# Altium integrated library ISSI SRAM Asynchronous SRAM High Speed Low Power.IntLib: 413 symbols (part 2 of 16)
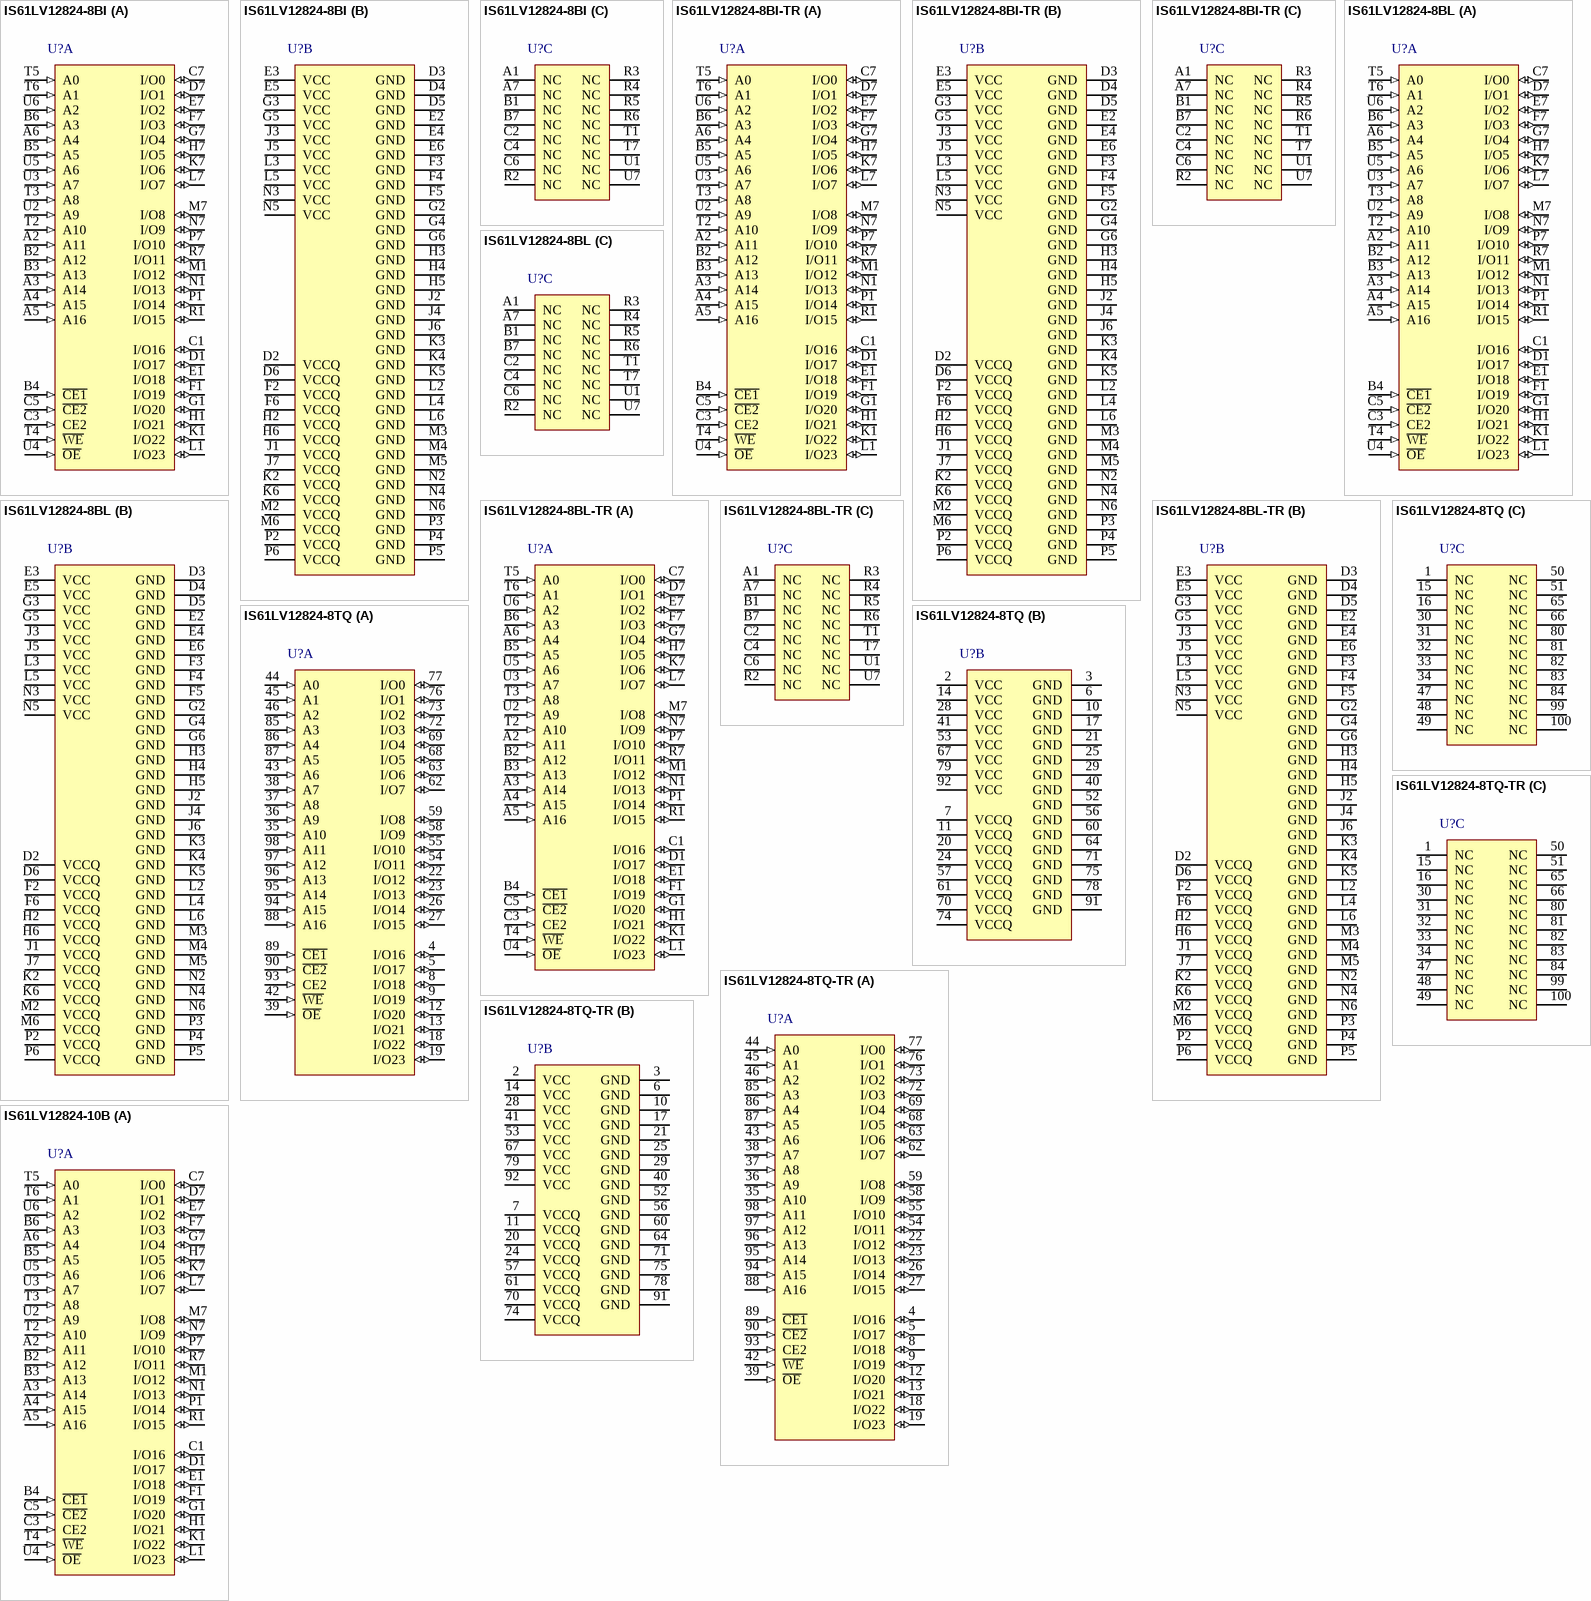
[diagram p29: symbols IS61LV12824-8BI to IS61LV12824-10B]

## IS61LV12824-8BI
designator U?
3 M High Speed CMOS SRAM with 3.3 V Supply, 128 K x 24, -40 to 85 degC, 119-Pin BGA (PBGA-119); Manufacturer: Integrated Silicon Solution Inc (ISSI); PartNumber: IS61LV12824-8BI; Density: 3M; Packing: Tray / Tube; Speed (ns): 8
footprint ISSI-PBGA-119-14000X22000DE_A (BGA, 119-Balls, Body 22x14mm, Pitch 1.27mm)
part A pins: A2 A11 (in) "Address Inputs", A3 A14 (in) "Address Inputs", A4 A15 (in) "Address Inputs", A5 A16 (in) "Address Inputs", A6 A4 (in) "Address Inputs", B2 A12 (in) "Address Inputs", B3 A13 (in) "Address Inputs", B4 ~{CE1} (in) "Chip Enable Input LOW", B5 A5 (in) "Address Input", B6 A3 (in) "Address Input", C1 I/O16 (io) "Data Inputs/Outputs", C3 CE2 (in) "Chip Enable Input HIGH", C5 ~{CE2} (in) "Chip Enable Input LOW", C7 I/O0 (io) "Data Inputs/Outputs", D1 I/O17 (io) "Data Inputs/Outputs", D7 I/O1 (io) "Data Inputs/Outputs", E1 I/O18 (io) "Data Inputs/Outputs", E7 I/O2 (io) "Data Inputs/Outputs", F1 I/O19 (io) "Data Inputs/Outputs", F7 I/O3 (io) "Data Inputs/Outputs", G1 I/O20 (io) "Data Inputs/Outputs", G7 I/O4 (io) "Data Inputs/Outputs", H1 I/O21 (io) "Data Inputs/Outputs", H7 I/O5 (io) "Data Inputs/Outputs", K1 I/O22 (io) "Data Inputs/Outputs", K7 I/O6 (io) "Data Inputs/Outputs", L1 I/O23 (io) "Data Inputs/Outputs", L7 I/O7 (io) "Data Inputs/Outputs", M1 I/O12 (io) "Data Inputs/Outputs", M7 I/O8 (io) "Data Inputs/Outputs", N1 I/O13 (io) "Data Inputs/Outputs", N7 I/O9 (io) "Data Inputs/Outputs", P1 I/O14 (io) "Data Inputs/Outputs", P7 I/O10 (io) "Data Inputs/Outputs", R1 I/O15 (io) "Data Inputs/Outputs", R7 I/O11 (io) "Data Inputs/Outputs", T2 A10 (in) "Address Inputs", T3 A8 (in) "Address Inputs", T4 ~{WE} (in) "Write Enable Input", T5 A0 (in) "Address Inputs", T6 A1 (in) "Address Inputs", U2 A9 (in) "Address Inputs", U3 A7 (in) "Address Inputs", U4 ~{OE} (in) "Output Enable Input", U5 A6 (in) "Address Inputs", U6 A2 (in) "Address Inputs"
part B pins: D2 VCCQ (power) "I/O Power", D3 GND (power) "Ground", D4 GND (power) "Ground", D5 GND (power) "Ground", D6 VCCQ (power) "I/O Power", E2 GND (power) "Ground", E3 VCC (power) "Power", E4 GND (power) "Ground", E5 VCC (power) "Power", E6 GND (power) "Ground", F2 VCCQ (power) "I/O Power", F3 GND (power) "Ground", F4 GND (power) "Ground", F5 GND (power) "Ground", F6 VCCQ (power) "I/O Power", G2 GND (power) "Ground", G3 VCC (power) "Power", G4 GND (power) "Ground", G5 VCC (power) "Power", G6 GND (power) "Ground", H2 VCCQ (power) "I/O Power", H3 GND (power) "Ground", H4 GND (power) "Ground", H5 GND (power) "Ground", H6 VCCQ (power) "I/O Power", J1 VCCQ (power) "I/O Power", J2 GND (power) "Ground", J3 VCC (power) "Power", J4 GND (power) "Ground", J5 VCC (power) "Power", J6 GND (power) "Ground", J7 VCCQ (power) "I/O Power", K2 VCCQ (power) "I/O Power", K3 GND (power) "Ground", K4 GND (power) "Ground", K5 GND (power) "Ground", K6 VCCQ (power) "I/O Power", L2 GND (power) "Ground", L3 VCC (power) "Power", L4 GND (power) "Ground", L5 VCC (power) "Power", L6 GND (power) "Ground", M2 VCCQ (power) "I/O Power", M3 GND (power) "Ground", M4 GND (power) "Ground", M5 GND (power) "Ground", M6 VCCQ (power) "I/O Power", N2 GND (power) "Ground", N3 VCC (power) "Power", N4 GND (power) "Ground", N5 VCC (power) "Power", N6 GND (power) "Ground", P2 VCCQ (power) "I/O Power", P3 GND (power) "Ground", P4 GND (power) "Ground", P5 GND (power) "Ground", P6 VCCQ (power) "I/O Power"
part C pins: A1 NC "No Connection", A7 NC "No Connection", B1 NC "No Connection", B7 NC "No Connection", C2 NC "No Connection", C4 NC "No Connection", C6 NC "No Connection", R2 NC "No Connection", R3 NC "No Connection", R4 NC "No Connection", R5 NC "No Connection", R6 NC "No Connection", T1 NC "No Connection", T7 NC "No Connection", U1 NC "No Connection", U7 NC "No Connection"

## IS61LV12824-8BI-TR
designator U?
3 M High Speed CMOS SRAM with 3.3 V Supply, 128 K x 24, -40 to 85 degC, 119-Pin BGA (PBGA-119); Manufacturer: Integrated Silicon Solution Inc (ISSI); PartNumber: IS61LV12824-8BI-TR; Density: 3M; Packing: Tape & Reel; Speed (ns): 8
footprint ISSI-PBGA-119-14000X22000DE_A (BGA, 119-Balls, Body 22x14mm, Pitch 1.27mm)
part A pins: A2 A11 (in) "Address Inputs", A3 A14 (in) "Address Inputs", A4 A15 (in) "Address Inputs", A5 A16 (in) "Address Inputs", A6 A4 (in) "Address Inputs", B2 A12 (in) "Address Inputs", B3 A13 (in) "Address Inputs", B4 ~{CE1} (in) "Chip Enable Input LOW", B5 A5 (in) "Address Input", B6 A3 (in) "Address Input", C1 I/O16 (io) "Data Inputs/Outputs", C3 CE2 (in) "Chip Enable Input HIGH", C5 ~{CE2} (in) "Chip Enable Input LOW", C7 I/O0 (io) "Data Inputs/Outputs", D1 I/O17 (io) "Data Inputs/Outputs", D7 I/O1 (io) "Data Inputs/Outputs", E1 I/O18 (io) "Data Inputs/Outputs", E7 I/O2 (io) "Data Inputs/Outputs", F1 I/O19 (io) "Data Inputs/Outputs", F7 I/O3 (io) "Data Inputs/Outputs", G1 I/O20 (io) "Data Inputs/Outputs", G7 I/O4 (io) "Data Inputs/Outputs", H1 I/O21 (io) "Data Inputs/Outputs", H7 I/O5 (io) "Data Inputs/Outputs", K1 I/O22 (io) "Data Inputs/Outputs", K7 I/O6 (io) "Data Inputs/Outputs", L1 I/O23 (io) "Data Inputs/Outputs", L7 I/O7 (io) "Data Inputs/Outputs", M1 I/O12 (io) "Data Inputs/Outputs", M7 I/O8 (io) "Data Inputs/Outputs", N1 I/O13 (io) "Data Inputs/Outputs", N7 I/O9 (io) "Data Inputs/Outputs", P1 I/O14 (io) "Data Inputs/Outputs", P7 I/O10 (io) "Data Inputs/Outputs", R1 I/O15 (io) "Data Inputs/Outputs", R7 I/O11 (io) "Data Inputs/Outputs", T2 A10 (in) "Address Inputs", T3 A8 (in) "Address Inputs", T4 ~{WE} (in) "Write Enable Input", T5 A0 (in) "Address Inputs", T6 A1 (in) "Address Inputs", U2 A9 (in) "Address Inputs", U3 A7 (in) "Address Inputs", U4 ~{OE} (in) "Output Enable Input", U5 A6 (in) "Address Inputs", U6 A2 (in) "Address Inputs"
part B pins: D2 VCCQ (power) "I/O Power", D3 GND (power) "Ground", D4 GND (power) "Ground", D5 GND (power) "Ground", D6 VCCQ (power) "I/O Power", E2 GND (power) "Ground", E3 VCC (power) "Power", E4 GND (power) "Ground", E5 VCC (power) "Power", E6 GND (power) "Ground", F2 VCCQ (power) "I/O Power", F3 GND (power) "Ground", F4 GND (power) "Ground", F5 GND (power) "Ground", F6 VCCQ (power) "I/O Power", G2 GND (power) "Ground", G3 VCC (power) "Power", G4 GND (power) "Ground", G5 VCC (power) "Power", G6 GND (power) "Ground", H2 VCCQ (power) "I/O Power", H3 GND (power) "Ground", H4 GND (power) "Ground", H5 GND (power) "Ground", H6 VCCQ (power) "I/O Power", J1 VCCQ (power) "I/O Power", J2 GND (power) "Ground", J3 VCC (power) "Power", J4 GND (power) "Ground", J5 VCC (power) "Power", J6 GND (power) "Ground", J7 VCCQ (power) "I/O Power", K2 VCCQ (power) "I/O Power", K3 GND (power) "Ground", K4 GND (power) "Ground", K5 GND (power) "Ground", K6 VCCQ (power) "I/O Power", L2 GND (power) "Ground", L3 VCC (power) "Power", L4 GND (power) "Ground", L5 VCC (power) "Power", L6 GND (power) "Ground", M2 VCCQ (power) "I/O Power", M3 GND (power) "Ground", M4 GND (power) "Ground", M5 GND (power) "Ground", M6 VCCQ (power) "I/O Power", N2 GND (power) "Ground", N3 VCC (power) "Power", N4 GND (power) "Ground", N5 VCC (power) "Power", N6 GND (power) "Ground", P2 VCCQ (power) "I/O Power", P3 GND (power) "Ground", P4 GND (power) "Ground", P5 GND (power) "Ground", P6 VCCQ (power) "I/O Power"
part C pins: A1 NC "No Connection", A7 NC "No Connection", B1 NC "No Connection", B7 NC "No Connection", C2 NC "No Connection", C4 NC "No Connection", C6 NC "No Connection", R2 NC "No Connection", R3 NC "No Connection", R4 NC "No Connection", R5 NC "No Connection", R6 NC "No Connection", T1 NC "No Connection", T7 NC "No Connection", U1 NC "No Connection", U7 NC "No Connection"

## IS61LV12824-8BL
designator U?
3 M High Speed CMOS SRAM with 3.3 V Supply, 128 K x 24, 0 to 70 degC, 119-Pin BGA (PBGA-119), Pb-Free; Manufacturer: Integrated Silicon Solution Inc (ISSI); PartNumber: IS61LV12824-8BL; Density: 3M; Packing: Tray / Tube; Speed (ns): 8
footprint ISSI-PBGA-119-14000X22000DE_A (BGA, 119-Balls, Body 22x14mm, Pitch 1.27mm)
part A pins: A2 A11 (in) "Address Inputs", A3 A14 (in) "Address Inputs", A4 A15 (in) "Address Inputs", A5 A16 (in) "Address Inputs", A6 A4 (in) "Address Inputs", B2 A12 (in) "Address Inputs", B3 A13 (in) "Address Inputs", B4 ~{CE1} (in) "Chip Enable Input LOW", B5 A5 (in) "Address Input", B6 A3 (in) "Address Input", C1 I/O16 (io) "Data Inputs/Outputs", C3 CE2 (in) "Chip Enable Input HIGH", C5 ~{CE2} (in) "Chip Enable Input LOW", C7 I/O0 (io) "Data Inputs/Outputs", D1 I/O17 (io) "Data Inputs/Outputs", D7 I/O1 (io) "Data Inputs/Outputs", E1 I/O18 (io) "Data Inputs/Outputs", E7 I/O2 (io) "Data Inputs/Outputs", F1 I/O19 (io) "Data Inputs/Outputs", F7 I/O3 (io) "Data Inputs/Outputs", G1 I/O20 (io) "Data Inputs/Outputs", G7 I/O4 (io) "Data Inputs/Outputs", H1 I/O21 (io) "Data Inputs/Outputs", H7 I/O5 (io) "Data Inputs/Outputs", K1 I/O22 (io) "Data Inputs/Outputs", K7 I/O6 (io) "Data Inputs/Outputs", L1 I/O23 (io) "Data Inputs/Outputs", L7 I/O7 (io) "Data Inputs/Outputs", M1 I/O12 (io) "Data Inputs/Outputs", M7 I/O8 (io) "Data Inputs/Outputs", N1 I/O13 (io) "Data Inputs/Outputs", N7 I/O9 (io) "Data Inputs/Outputs", P1 I/O14 (io) "Data Inputs/Outputs", P7 I/O10 (io) "Data Inputs/Outputs", R1 I/O15 (io) "Data Inputs/Outputs", R7 I/O11 (io) "Data Inputs/Outputs", T2 A10 (in) "Address Inputs", T3 A8 (in) "Address Inputs", T4 ~{WE} (in) "Write Enable Input", T5 A0 (in) "Address Inputs", T6 A1 (in) "Address Inputs", U2 A9 (in) "Address Inputs", U3 A7 (in) "Address Inputs", U4 ~{OE} (in) "Output Enable Input", U5 A6 (in) "Address Inputs", U6 A2 (in) "Address Inputs"
part B pins: D2 VCCQ (power) "I/O Power", D3 GND (power) "Ground", D4 GND (power) "Ground", D5 GND (power) "Ground", D6 VCCQ (power) "I/O Power", E2 GND (power) "Ground", E3 VCC (power) "Power", E4 GND (power) "Ground", E5 VCC (power) "Power", E6 GND (power) "Ground", F2 VCCQ (power) "I/O Power", F3 GND (power) "Ground", F4 GND (power) "Ground", F5 GND (power) "Ground", F6 VCCQ (power) "I/O Power", G2 GND (power) "Ground", G3 VCC (power) "Power", G4 GND (power) "Ground", G5 VCC (power) "Power", G6 GND (power) "Ground", H2 VCCQ (power) "I/O Power", H3 GND (power) "Ground", H4 GND (power) "Ground", H5 GND (power) "Ground", H6 VCCQ (power) "I/O Power", J1 VCCQ (power) "I/O Power", J2 GND (power) "Ground", J3 VCC (power) "Power", J4 GND (power) "Ground", J5 VCC (power) "Power", J6 GND (power) "Ground", J7 VCCQ (power) "I/O Power", K2 VCCQ (power) "I/O Power", K3 GND (power) "Ground", K4 GND (power) "Ground", K5 GND (power) "Ground", K6 VCCQ (power) "I/O Power", L2 GND (power) "Ground", L3 VCC (power) "Power", L4 GND (power) "Ground", L5 VCC (power) "Power", L6 GND (power) "Ground", M2 VCCQ (power) "I/O Power", M3 GND (power) "Ground", M4 GND (power) "Ground", M5 GND (power) "Ground", M6 VCCQ (power) "I/O Power", N2 GND (power) "Ground", N3 VCC (power) "Power", N4 GND (power) "Ground", N5 VCC (power) "Power", N6 GND (power) "Ground", P2 VCCQ (power) "I/O Power", P3 GND (power) "Ground", P4 GND (power) "Ground", P5 GND (power) "Ground", P6 VCCQ (power) "I/O Power"
part C pins: A1 NC "No Connection", A7 NC "No Connection", B1 NC "No Connection", B7 NC "No Connection", C2 NC "No Connection", C4 NC "No Connection", C6 NC "No Connection", R2 NC "No Connection", R3 NC "No Connection", R4 NC "No Connection", R5 NC "No Connection", R6 NC "No Connection", T1 NC "No Connection", T7 NC "No Connection", U1 NC "No Connection", U7 NC "No Connection"

## IS61LV12824-8BL-TR
designator U?
3 M High Speed CMOS SRAM with 3.3 V Supply, 128 K x 24, 0 to 70 degC, 119-Pin BGA (PBGA-119), Pb-Free; Manufacturer: Integrated Silicon Solution Inc (ISSI); PartNumber: IS61LV12824-8BL-TR; Density: 3M; Packing: Tape & Reel; Speed (ns): 8
footprint ISSI-PBGA-119-14000X22000DE_A (BGA, 119-Balls, Body 22x14mm, Pitch 1.27mm)
part A pins: A2 A11 (in) "Address Inputs", A3 A14 (in) "Address Inputs", A4 A15 (in) "Address Inputs", A5 A16 (in) "Address Inputs", A6 A4 (in) "Address Inputs", B2 A12 (in) "Address Inputs", B3 A13 (in) "Address Inputs", B4 ~{CE1} (in) "Chip Enable Input LOW", B5 A5 (in) "Address Input", B6 A3 (in) "Address Input", C1 I/O16 (io) "Data Inputs/Outputs", C3 CE2 (in) "Chip Enable Input HIGH", C5 ~{CE2} (in) "Chip Enable Input LOW", C7 I/O0 (io) "Data Inputs/Outputs", D1 I/O17 (io) "Data Inputs/Outputs", D7 I/O1 (io) "Data Inputs/Outputs", E1 I/O18 (io) "Data Inputs/Outputs", E7 I/O2 (io) "Data Inputs/Outputs", F1 I/O19 (io) "Data Inputs/Outputs", F7 I/O3 (io) "Data Inputs/Outputs", G1 I/O20 (io) "Data Inputs/Outputs", G7 I/O4 (io) "Data Inputs/Outputs", H1 I/O21 (io) "Data Inputs/Outputs", H7 I/O5 (io) "Data Inputs/Outputs", K1 I/O22 (io) "Data Inputs/Outputs", K7 I/O6 (io) "Data Inputs/Outputs", L1 I/O23 (io) "Data Inputs/Outputs", L7 I/O7 (io) "Data Inputs/Outputs", M1 I/O12 (io) "Data Inputs/Outputs", M7 I/O8 (io) "Data Inputs/Outputs", N1 I/O13 (io) "Data Inputs/Outputs", N7 I/O9 (io) "Data Inputs/Outputs", P1 I/O14 (io) "Data Inputs/Outputs", P7 I/O10 (io) "Data Inputs/Outputs", R1 I/O15 (io) "Data Inputs/Outputs", R7 I/O11 (io) "Data Inputs/Outputs", T2 A10 (in) "Address Inputs", T3 A8 (in) "Address Inputs", T4 ~{WE} (in) "Write Enable Input", T5 A0 (in) "Address Inputs", T6 A1 (in) "Address Inputs", U2 A9 (in) "Address Inputs", U3 A7 (in) "Address Inputs", U4 ~{OE} (in) "Output Enable Input", U5 A6 (in) "Address Inputs", U6 A2 (in) "Address Inputs"
part B pins: D2 VCCQ (power) "I/O Power", D3 GND (power) "Ground", D4 GND (power) "Ground", D5 GND (power) "Ground", D6 VCCQ (power) "I/O Power", E2 GND (power) "Ground", E3 VCC (power) "Power", E4 GND (power) "Ground", E5 VCC (power) "Power", E6 GND (power) "Ground", F2 VCCQ (power) "I/O Power", F3 GND (power) "Ground", F4 GND (power) "Ground", F5 GND (power) "Ground", F6 VCCQ (power) "I/O Power", G2 GND (power) "Ground", G3 VCC (power) "Power", G4 GND (power) "Ground", G5 VCC (power) "Power", G6 GND (power) "Ground", H2 VCCQ (power) "I/O Power", H3 GND (power) "Ground", H4 GND (power) "Ground", H5 GND (power) "Ground", H6 VCCQ (power) "I/O Power", J1 VCCQ (power) "I/O Power", J2 GND (power) "Ground", J3 VCC (power) "Power", J4 GND (power) "Ground", J5 VCC (power) "Power", J6 GND (power) "Ground", J7 VCCQ (power) "I/O Power", K2 VCCQ (power) "I/O Power", K3 GND (power) "Ground", K4 GND (power) "Ground", K5 GND (power) "Ground", K6 VCCQ (power) "I/O Power", L2 GND (power) "Ground", L3 VCC (power) "Power", L4 GND (power) "Ground", L5 VCC (power) "Power", L6 GND (power) "Ground", M2 VCCQ (power) "I/O Power", M3 GND (power) "Ground", M4 GND (power) "Ground", M5 GND (power) "Ground", M6 VCCQ (power) "I/O Power", N2 GND (power) "Ground", N3 VCC (power) "Power", N4 GND (power) "Ground", N5 VCC (power) "Power", N6 GND (power) "Ground", P2 VCCQ (power) "I/O Power", P3 GND (power) "Ground", P4 GND (power) "Ground", P5 GND (power) "Ground", P6 VCCQ (power) "I/O Power"
part C pins: A1 NC "No Connection", A7 NC "No Connection", B1 NC "No Connection", B7 NC "No Connection", C2 NC "No Connection", C4 NC "No Connection", C6 NC "No Connection", R2 NC "No Connection", R3 NC "No Connection", R4 NC "No Connection", R5 NC "No Connection", R6 NC "No Connection", T1 NC "No Connection", T7 NC "No Connection", U1 NC "No Connection", U7 NC "No Connection"

## IS61LV12824-8TQ
designator U?
3 M High Speed CMOS SRAM with 3.3 V Supply, 128 K x 24, 0 to 70 degC, 100-Pin QFP (TQFP-100); Manufacturer: Integrated Silicon Solution Inc (ISSI); PartNumber: IS61LV12824-8TQ; Density: 3M; Packing: Tray / Tube; Speed (ns): 8
footprint ISSI-TQFP-100-20000X14000DE_N (QFP, 100-Leads, Body 20x14mm, Pitch 0.65mm, IPC Medium Density)
part A pins: 4 I/O16 (io) "Data Input/Output", 5 I/O17 (io) "Data Input/Output", 8 I/O18 (io) "Data Input/Output", 9 I/O19 (io) "Data Input/Output", 12 I/O20 (io) "Data Input/Output", 13 I/O21 (io) "Data Input/Output", 18 I/O22 (io) "Data Input/Output", 19 I/O23 (io) "Data Input/Output", 22 I/O12 (io) "Data Input/Output", 23 I/O13 (io) "Data Input/Output", 26 I/O14 (io) "Data Input/Output", 27 I/O15 (io) "Data Input/Output", 35 A10 (in) "Address Input", 36 A9 (in) "Address Input", 37 A8 (in) "Address Input", 38 A7 (in) "Address Input", 39 ~{OE} (in) "Output Enable Input", 42 ~{WE} (in) "Write Enable Input", 43 A6 (in) "Address Input", 44 A0 (in) "Address Input", 45 A1 (in) "Address Input", 46 A2 (in) "Address Input", 54 I/O11 (io) "Data Input/Output", 55 I/O10 (io) "Data Input/Output", 58 I/O9 (io) "Data Input/Output", 59 I/O8 (io) "Data Input/Output", 62 I/O7 (io) "Data Input/Output", 63 I/O6 (io) "Data Input/Output", 68 I/O5 (io) "Data Input/Output", 69 I/O4 (io) "Data Input/Output", 72 I/O3 (io) "Data Input/Output", 73 I/O2 (io) "Data Input/Output", 76 I/O1 (io) "Data Input/Output", 77 I/O0 (io) "Data Input/Output", 85 A3 (in) "Address Input", 86 A4 (in) "Address Input", 87 A5 (in) "Address Input", 88 A16 (in) "Address Input", 89 ~{CE1} (in) "Chip Enable Input LOW", 90 ~{CE2} (in) "Chip Enable Input LOW", 93 CE2 (in) "Chip Enable Input HIGH", 94 A15 (in) "Address Input", 95 A14 (in) "Address Input", 96 A13 (in) "Address Input", 97 A12 (in) "Address Input", 98 A11 (in) "Address Input"
part B pins: 2 VCC (power) "Power", 3 GND (power) "Ground", 6 GND (power) "Ground", 7 VCCQ (power) "I/O Power", 10 GND (power) "Ground", 11 VCCQ (power) "I/O Power", 14 VCC (power) "Power", 17 GND (power) "Ground", 20 VCCQ (power) "I/O Power", 21 GND (power) "Ground", 24 VCCQ (power) "I/O Power", 25 GND (power) "Ground", 28 VCC (power) "Power", 29 GND (power) "Ground", 40 GND (power) "Ground", 41 VCC (power) "Power", 52 GND (power) "Ground", 53 VCC (power) "Power", 56 GND (power) "Ground", 57 VCCQ (power) "I/O Power", 60 GND (power) "Ground", 61 VCCQ (power) "I/O Power", 64 GND (power) "Ground", 67 VCC (power) "Power", 70 VCCQ (power) "I/O Power", 71 GND (power) "Ground", 74 VCCQ (power) "I/O Power", 75 GND (power) "Ground", 78 GND (power) "Ground", 79 VCC (power) "Power", 91 GND (power) "Ground", 92 VCC (power) "Power"
part C pins: 1 NC "No Connection", 15 NC "No Connection", 16 NC "No Connection", 30 NC "No Connection", 31 NC "No Connection", 32 NC "No Connection", 33 NC "No Connection", 34 NC "No Connection", 47 NC "No Connection", 48 NC "No Connection", 49 NC "No Connection", 50 NC "No Connection", 51 NC "No Connection", 65 NC "No Connection", 66 NC "No Connection", 80 NC "No Connection", 81 NC "No Connection", 82 NC "No Connection", 83 NC "No Connection", 84 NC "No Connection", 99 NC "No Connection", 100 NC "No Connection"

## IS61LV12824-8TQ-TR
designator U?
3 M High Speed CMOS SRAM with 3.3 V Supply, 128 K x 24, 0 to 70 degC, 100-Pin QFP (TQFP-100); Manufacturer: Integrated Silicon Solution Inc (ISSI); PartNumber: IS61LV12824-8TQ-TR; Density: 3M; Packing: Tape & Reel; Speed (ns): 8
footprint ISSI-TQFP-100-20000X14000DE_N (QFP, 100-Leads, Body 20x14mm, Pitch 0.65mm, IPC Medium Density)
part A pins: 4 I/O16 (io) "Data Input/Output", 5 I/O17 (io) "Data Input/Output", 8 I/O18 (io) "Data Input/Output", 9 I/O19 (io) "Data Input/Output", 12 I/O20 (io) "Data Input/Output", 13 I/O21 (io) "Data Input/Output", 18 I/O22 (io) "Data Input/Output", 19 I/O23 (io) "Data Input/Output", 22 I/O12 (io) "Data Input/Output", 23 I/O13 (io) "Data Input/Output", 26 I/O14 (io) "Data Input/Output", 27 I/O15 (io) "Data Input/Output", 35 A10 (in) "Address Input", 36 A9 (in) "Address Input", 37 A8 (in) "Address Input", 38 A7 (in) "Address Input", 39 ~{OE} (in) "Output Enable Input", 42 ~{WE} (in) "Write Enable Input", 43 A6 (in) "Address Input", 44 A0 (in) "Address Input", 45 A1 (in) "Address Input", 46 A2 (in) "Address Input", 54 I/O11 (io) "Data Input/Output", 55 I/O10 (io) "Data Input/Output", 58 I/O9 (io) "Data Input/Output", 59 I/O8 (io) "Data Input/Output", 62 I/O7 (io) "Data Input/Output", 63 I/O6 (io) "Data Input/Output", 68 I/O5 (io) "Data Input/Output", 69 I/O4 (io) "Data Input/Output", 72 I/O3 (io) "Data Input/Output", 73 I/O2 (io) "Data Input/Output", 76 I/O1 (io) "Data Input/Output", 77 I/O0 (io) "Data Input/Output", 85 A3 (in) "Address Input", 86 A4 (in) "Address Input", 87 A5 (in) "Address Input", 88 A16 (in) "Address Input", 89 ~{CE1} (in) "Chip Enable Input LOW", 90 ~{CE2} (in) "Chip Enable Input LOW", 93 CE2 (in) "Chip Enable Input HIGH", 94 A15 (in) "Address Input", 95 A14 (in) "Address Input", 96 A13 (in) "Address Input", 97 A12 (in) "Address Input", 98 A11 (in) "Address Input"
part B pins: 2 VCC (power) "Power", 3 GND (power) "Ground", 6 GND (power) "Ground", 7 VCCQ (power) "I/O Power", 10 GND (power) "Ground", 11 VCCQ (power) "I/O Power", 14 VCC (power) "Power", 17 GND (power) "Ground", 20 VCCQ (power) "I/O Power", 21 GND (power) "Ground", 24 VCCQ (power) "I/O Power", 25 GND (power) "Ground", 28 VCC (power) "Power", 29 GND (power) "Ground", 40 GND (power) "Ground", 41 VCC (power) "Power", 52 GND (power) "Ground", 53 VCC (power) "Power", 56 GND (power) "Ground", 57 VCCQ (power) "I/O Power", 60 GND (power) "Ground", 61 VCCQ (power) "I/O Power", 64 GND (power) "Ground", 67 VCC (power) "Power", 70 VCCQ (power) "I/O Power", 71 GND (power) "Ground", 74 VCCQ (power) "I/O Power", 75 GND (power) "Ground", 78 GND (power) "Ground", 79 VCC (power) "Power", 91 GND (power) "Ground", 92 VCC (power) "Power"
part C pins: 1 NC "No Connection", 15 NC "No Connection", 16 NC "No Connection", 30 NC "No Connection", 31 NC "No Connection", 32 NC "No Connection", 33 NC "No Connection", 34 NC "No Connection", 47 NC "No Connection", 48 NC "No Connection", 49 NC "No Connection", 50 NC "No Connection", 51 NC "No Connection", 65 NC "No Connection", 66 NC "No Connection", 80 NC "No Connection", 81 NC "No Connection", 82 NC "No Connection", 83 NC "No Connection", 84 NC "No Connection", 99 NC "No Connection", 100 NC "No Connection"

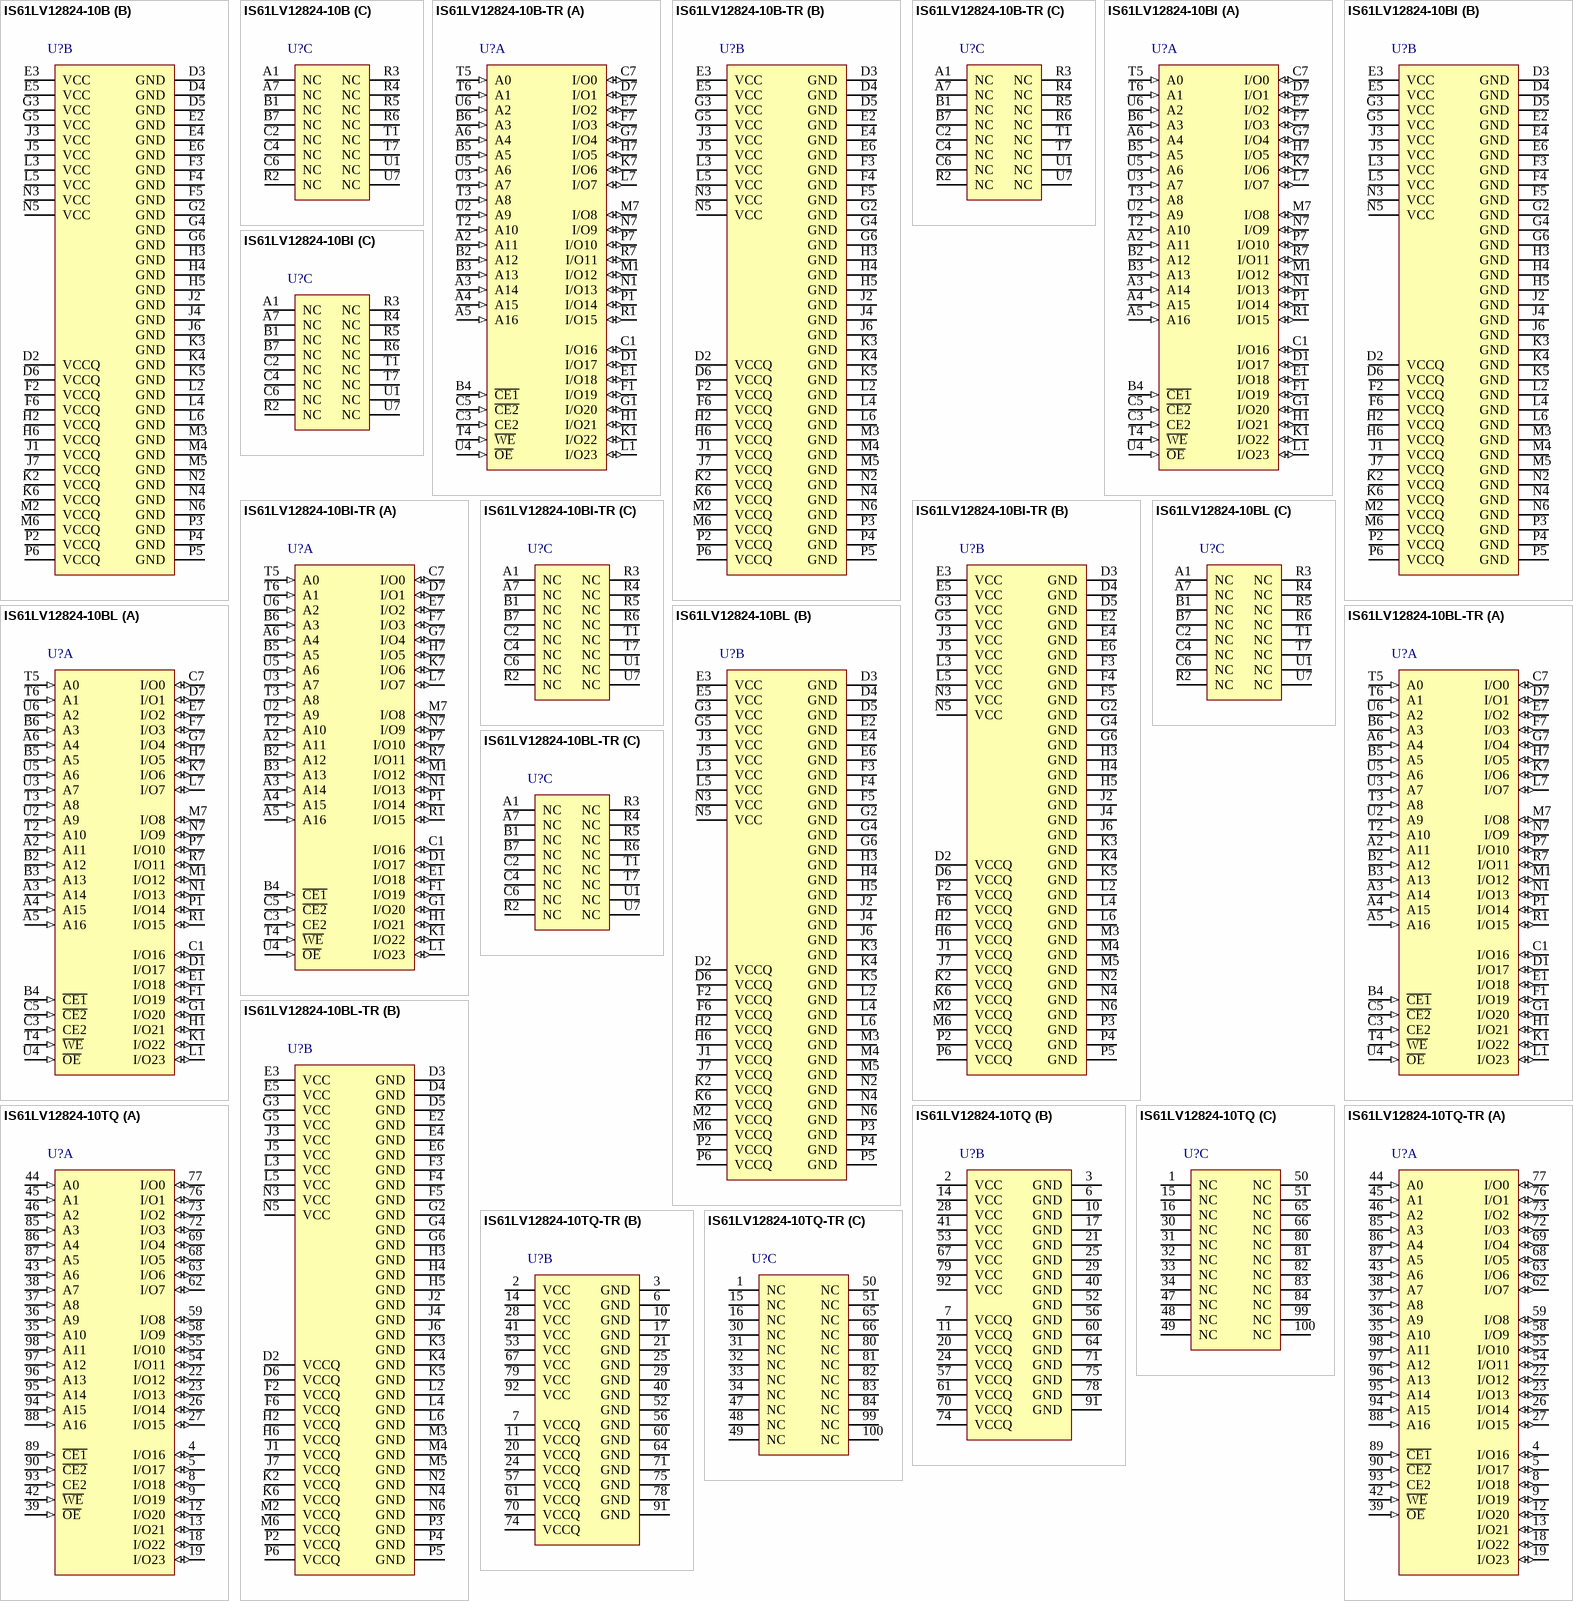
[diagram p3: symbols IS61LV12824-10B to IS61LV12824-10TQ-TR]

## IS61LV12824-10B
designator U?
3 M High Speed CMOS SRAM with 3.3 V Supply, 128 K x 24, 0 to 70 degC, 119-Pin BGA (PBGA-119); Manufacturer: Integrated Silicon Solution Inc (ISSI); PartNumber: IS61LV12824-10B; Density: 3M; Packing: Tray / Tube; Speed (ns): 10
footprint ISSI-PBGA-119-14000X22000DE_A (BGA, 119-Balls, Body 22x14mm, Pitch 1.27mm)
part A pins: A2 A11 (in) "Address Inputs", A3 A14 (in) "Address Inputs", A4 A15 (in) "Address Inputs", A5 A16 (in) "Address Inputs", A6 A4 (in) "Address Inputs", B2 A12 (in) "Address Inputs", B3 A13 (in) "Address Inputs", B4 ~{CE1} (in) "Chip Enable Input LOW", B5 A5 (in) "Address Input", B6 A3 (in) "Address Input", C1 I/O16 (io) "Data Inputs/Outputs", C3 CE2 (in) "Chip Enable Input HIGH", C5 ~{CE2} (in) "Chip Enable Input LOW", C7 I/O0 (io) "Data Inputs/Outputs", D1 I/O17 (io) "Data Inputs/Outputs", D7 I/O1 (io) "Data Inputs/Outputs", E1 I/O18 (io) "Data Inputs/Outputs", E7 I/O2 (io) "Data Inputs/Outputs", F1 I/O19 (io) "Data Inputs/Outputs", F7 I/O3 (io) "Data Inputs/Outputs", G1 I/O20 (io) "Data Inputs/Outputs", G7 I/O4 (io) "Data Inputs/Outputs", H1 I/O21 (io) "Data Inputs/Outputs", H7 I/O5 (io) "Data Inputs/Outputs", K1 I/O22 (io) "Data Inputs/Outputs", K7 I/O6 (io) "Data Inputs/Outputs", L1 I/O23 (io) "Data Inputs/Outputs", L7 I/O7 (io) "Data Inputs/Outputs", M1 I/O12 (io) "Data Inputs/Outputs", M7 I/O8 (io) "Data Inputs/Outputs", N1 I/O13 (io) "Data Inputs/Outputs", N7 I/O9 (io) "Data Inputs/Outputs", P1 I/O14 (io) "Data Inputs/Outputs", P7 I/O10 (io) "Data Inputs/Outputs", R1 I/O15 (io) "Data Inputs/Outputs", R7 I/O11 (io) "Data Inputs/Outputs", T2 A10 (in) "Address Inputs", T3 A8 (in) "Address Inputs", T4 ~{WE} (in) "Write Enable Input", T5 A0 (in) "Address Inputs", T6 A1 (in) "Address Inputs", U2 A9 (in) "Address Inputs", U3 A7 (in) "Address Inputs", U4 ~{OE} (in) "Output Enable Input", U5 A6 (in) "Address Inputs", U6 A2 (in) "Address Inputs"
part B pins: D2 VCCQ (power) "I/O Power", D3 GND (power) "Ground", D4 GND (power) "Ground", D5 GND (power) "Ground", D6 VCCQ (power) "I/O Power", E2 GND (power) "Ground", E3 VCC (power) "Power", E4 GND (power) "Ground", E5 VCC (power) "Power", E6 GND (power) "Ground", F2 VCCQ (power) "I/O Power", F3 GND (power) "Ground", F4 GND (power) "Ground", F5 GND (power) "Ground", F6 VCCQ (power) "I/O Power", G2 GND (power) "Ground", G3 VCC (power) "Power", G4 GND (power) "Ground", G5 VCC (power) "Power", G6 GND (power) "Ground", H2 VCCQ (power) "I/O Power", H3 GND (power) "Ground", H4 GND (power) "Ground", H5 GND (power) "Ground", H6 VCCQ (power) "I/O Power", J1 VCCQ (power) "I/O Power", J2 GND (power) "Ground", J3 VCC (power) "Power", J4 GND (power) "Ground", J5 VCC (power) "Power", J6 GND (power) "Ground", J7 VCCQ (power) "I/O Power", K2 VCCQ (power) "I/O Power", K3 GND (power) "Ground", K4 GND (power) "Ground", K5 GND (power) "Ground", K6 VCCQ (power) "I/O Power", L2 GND (power) "Ground", L3 VCC (power) "Power", L4 GND (power) "Ground", L5 VCC (power) "Power", L6 GND (power) "Ground", M2 VCCQ (power) "I/O Power", M3 GND (power) "Ground", M4 GND (power) "Ground", M5 GND (power) "Ground", M6 VCCQ (power) "I/O Power", N2 GND (power) "Ground", N3 VCC (power) "Power", N4 GND (power) "Ground", N5 VCC (power) "Power", N6 GND (power) "Ground", P2 VCCQ (power) "I/O Power", P3 GND (power) "Ground", P4 GND (power) "Ground", P5 GND (power) "Ground", P6 VCCQ (power) "I/O Power"
part C pins: A1 NC "No Connection", A7 NC "No Connection", B1 NC "No Connection", B7 NC "No Connection", C2 NC "No Connection", C4 NC "No Connection", C6 NC "No Connection", R2 NC "No Connection", R3 NC "No Connection", R4 NC "No Connection", R5 NC "No Connection", R6 NC "No Connection", T1 NC "No Connection", T7 NC "No Connection", U1 NC "No Connection", U7 NC "No Connection"

## IS61LV12824-10B-TR
designator U?
3 M High Speed CMOS SRAM with 3.3 V Supply, 128 K x 24, 0 to 70 degC, 119-Pin BGA (PBGA-119); Manufacturer: Integrated Silicon Solution Inc (ISSI); PartNumber: IS61LV12824-10B-TR; Density: 3M; Packing: Tape & Reel; Speed (ns): 10
footprint ISSI-PBGA-119-14000X22000DE_A (BGA, 119-Balls, Body 22x14mm, Pitch 1.27mm)
part A pins: A2 A11 (in) "Address Inputs", A3 A14 (in) "Address Inputs", A4 A15 (in) "Address Inputs", A5 A16 (in) "Address Inputs", A6 A4 (in) "Address Inputs", B2 A12 (in) "Address Inputs", B3 A13 (in) "Address Inputs", B4 ~{CE1} (in) "Chip Enable Input LOW", B5 A5 (in) "Address Input", B6 A3 (in) "Address Input", C1 I/O16 (io) "Data Inputs/Outputs", C3 CE2 (in) "Chip Enable Input HIGH", C5 ~{CE2} (in) "Chip Enable Input LOW", C7 I/O0 (io) "Data Inputs/Outputs", D1 I/O17 (io) "Data Inputs/Outputs", D7 I/O1 (io) "Data Inputs/Outputs", E1 I/O18 (io) "Data Inputs/Outputs", E7 I/O2 (io) "Data Inputs/Outputs", F1 I/O19 (io) "Data Inputs/Outputs", F7 I/O3 (io) "Data Inputs/Outputs", G1 I/O20 (io) "Data Inputs/Outputs", G7 I/O4 (io) "Data Inputs/Outputs", H1 I/O21 (io) "Data Inputs/Outputs", H7 I/O5 (io) "Data Inputs/Outputs", K1 I/O22 (io) "Data Inputs/Outputs", K7 I/O6 (io) "Data Inputs/Outputs", L1 I/O23 (io) "Data Inputs/Outputs", L7 I/O7 (io) "Data Inputs/Outputs", M1 I/O12 (io) "Data Inputs/Outputs", M7 I/O8 (io) "Data Inputs/Outputs", N1 I/O13 (io) "Data Inputs/Outputs", N7 I/O9 (io) "Data Inputs/Outputs", P1 I/O14 (io) "Data Inputs/Outputs", P7 I/O10 (io) "Data Inputs/Outputs", R1 I/O15 (io) "Data Inputs/Outputs", R7 I/O11 (io) "Data Inputs/Outputs", T2 A10 (in) "Address Inputs", T3 A8 (in) "Address Inputs", T4 ~{WE} (in) "Write Enable Input", T5 A0 (in) "Address Inputs", T6 A1 (in) "Address Inputs", U2 A9 (in) "Address Inputs", U3 A7 (in) "Address Inputs", U4 ~{OE} (in) "Output Enable Input", U5 A6 (in) "Address Inputs", U6 A2 (in) "Address Inputs"
part B pins: D2 VCCQ (power) "I/O Power", D3 GND (power) "Ground", D4 GND (power) "Ground", D5 GND (power) "Ground", D6 VCCQ (power) "I/O Power", E2 GND (power) "Ground", E3 VCC (power) "Power", E4 GND (power) "Ground", E5 VCC (power) "Power", E6 GND (power) "Ground", F2 VCCQ (power) "I/O Power", F3 GND (power) "Ground", F4 GND (power) "Ground", F5 GND (power) "Ground", F6 VCCQ (power) "I/O Power", G2 GND (power) "Ground", G3 VCC (power) "Power", G4 GND (power) "Ground", G5 VCC (power) "Power", G6 GND (power) "Ground", H2 VCCQ (power) "I/O Power", H3 GND (power) "Ground", H4 GND (power) "Ground", H5 GND (power) "Ground", H6 VCCQ (power) "I/O Power", J1 VCCQ (power) "I/O Power", J2 GND (power) "Ground", J3 VCC (power) "Power", J4 GND (power) "Ground", J5 VCC (power) "Power", J6 GND (power) "Ground", J7 VCCQ (power) "I/O Power", K2 VCCQ (power) "I/O Power", K3 GND (power) "Ground", K4 GND (power) "Ground", K5 GND (power) "Ground", K6 VCCQ (power) "I/O Power", L2 GND (power) "Ground", L3 VCC (power) "Power", L4 GND (power) "Ground", L5 VCC (power) "Power", L6 GND (power) "Ground", M2 VCCQ (power) "I/O Power", M3 GND (power) "Ground", M4 GND (power) "Ground", M5 GND (power) "Ground", M6 VCCQ (power) "I/O Power", N2 GND (power) "Ground", N3 VCC (power) "Power", N4 GND (power) "Ground", N5 VCC (power) "Power", N6 GND (power) "Ground", P2 VCCQ (power) "I/O Power", P3 GND (power) "Ground", P4 GND (power) "Ground", P5 GND (power) "Ground", P6 VCCQ (power) "I/O Power"
part C pins: A1 NC "No Connection", A7 NC "No Connection", B1 NC "No Connection", B7 NC "No Connection", C2 NC "No Connection", C4 NC "No Connection", C6 NC "No Connection", R2 NC "No Connection", R3 NC "No Connection", R4 NC "No Connection", R5 NC "No Connection", R6 NC "No Connection", T1 NC "No Connection", T7 NC "No Connection", U1 NC "No Connection", U7 NC "No Connection"

## IS61LV12824-10BI
designator U?
3 M High Speed CMOS SRAM with 3.3 V Supply, 128 K x 24, -40 to 85 degC, 119-Pin BGA (PBGA-119); Manufacturer: Integrated Silicon Solution Inc (ISSI); PartNumber: IS61LV12824-10BI; Density: 3M; Packing: Tray / Tube; Speed (ns): 10
footprint ISSI-PBGA-119-14000X22000DE_A (BGA, 119-Balls, Body 22x14mm, Pitch 1.27mm)
part A pins: A2 A11 (in) "Address Inputs", A3 A14 (in) "Address Inputs", A4 A15 (in) "Address Inputs", A5 A16 (in) "Address Inputs", A6 A4 (in) "Address Inputs", B2 A12 (in) "Address Inputs", B3 A13 (in) "Address Inputs", B4 ~{CE1} (in) "Chip Enable Input LOW", B5 A5 (in) "Address Input", B6 A3 (in) "Address Input", C1 I/O16 (io) "Data Inputs/Outputs", C3 CE2 (in) "Chip Enable Input HIGH", C5 ~{CE2} (in) "Chip Enable Input LOW", C7 I/O0 (io) "Data Inputs/Outputs", D1 I/O17 (io) "Data Inputs/Outputs", D7 I/O1 (io) "Data Inputs/Outputs", E1 I/O18 (io) "Data Inputs/Outputs", E7 I/O2 (io) "Data Inputs/Outputs", F1 I/O19 (io) "Data Inputs/Outputs", F7 I/O3 (io) "Data Inputs/Outputs", G1 I/O20 (io) "Data Inputs/Outputs", G7 I/O4 (io) "Data Inputs/Outputs", H1 I/O21 (io) "Data Inputs/Outputs", H7 I/O5 (io) "Data Inputs/Outputs", K1 I/O22 (io) "Data Inputs/Outputs", K7 I/O6 (io) "Data Inputs/Outputs", L1 I/O23 (io) "Data Inputs/Outputs", L7 I/O7 (io) "Data Inputs/Outputs", M1 I/O12 (io) "Data Inputs/Outputs", M7 I/O8 (io) "Data Inputs/Outputs", N1 I/O13 (io) "Data Inputs/Outputs", N7 I/O9 (io) "Data Inputs/Outputs", P1 I/O14 (io) "Data Inputs/Outputs", P7 I/O10 (io) "Data Inputs/Outputs", R1 I/O15 (io) "Data Inputs/Outputs", R7 I/O11 (io) "Data Inputs/Outputs", T2 A10 (in) "Address Inputs", T3 A8 (in) "Address Inputs", T4 ~{WE} (in) "Write Enable Input", T5 A0 (in) "Address Inputs", T6 A1 (in) "Address Inputs", U2 A9 (in) "Address Inputs", U3 A7 (in) "Address Inputs", U4 ~{OE} (in) "Output Enable Input", U5 A6 (in) "Address Inputs", U6 A2 (in) "Address Inputs"
part B pins: D2 VCCQ (power) "I/O Power", D3 GND (power) "Ground", D4 GND (power) "Ground", D5 GND (power) "Ground", D6 VCCQ (power) "I/O Power", E2 GND (power) "Ground", E3 VCC (power) "Power", E4 GND (power) "Ground", E5 VCC (power) "Power", E6 GND (power) "Ground", F2 VCCQ (power) "I/O Power", F3 GND (power) "Ground", F4 GND (power) "Ground", F5 GND (power) "Ground", F6 VCCQ (power) "I/O Power", G2 GND (power) "Ground", G3 VCC (power) "Power", G4 GND (power) "Ground", G5 VCC (power) "Power", G6 GND (power) "Ground", H2 VCCQ (power) "I/O Power", H3 GND (power) "Ground", H4 GND (power) "Ground", H5 GND (power) "Ground", H6 VCCQ (power) "I/O Power", J1 VCCQ (power) "I/O Power", J2 GND (power) "Ground", J3 VCC (power) "Power", J4 GND (power) "Ground", J5 VCC (power) "Power", J6 GND (power) "Ground", J7 VCCQ (power) "I/O Power", K2 VCCQ (power) "I/O Power", K3 GND (power) "Ground", K4 GND (power) "Ground", K5 GND (power) "Ground", K6 VCCQ (power) "I/O Power", L2 GND (power) "Ground", L3 VCC (power) "Power", L4 GND (power) "Ground", L5 VCC (power) "Power", L6 GND (power) "Ground", M2 VCCQ (power) "I/O Power", M3 GND (power) "Ground", M4 GND (power) "Ground", M5 GND (power) "Ground", M6 VCCQ (power) "I/O Power", N2 GND (power) "Ground", N3 VCC (power) "Power", N4 GND (power) "Ground", N5 VCC (power) "Power", N6 GND (power) "Ground", P2 VCCQ (power) "I/O Power", P3 GND (power) "Ground", P4 GND (power) "Ground", P5 GND (power) "Ground", P6 VCCQ (power) "I/O Power"
part C pins: A1 NC "No Connection", A7 NC "No Connection", B1 NC "No Connection", B7 NC "No Connection", C2 NC "No Connection", C4 NC "No Connection", C6 NC "No Connection", R2 NC "No Connection", R3 NC "No Connection", R4 NC "No Connection", R5 NC "No Connection", R6 NC "No Connection", T1 NC "No Connection", T7 NC "No Connection", U1 NC "No Connection", U7 NC "No Connection"

## IS61LV12824-10BI-TR
designator U?
3 M High Speed CMOS SRAM with 3.3 V Supply, 128 K x 24, -40 to 85 degC, 119-Pin BGA (PBGA-119); Manufacturer: Integrated Silicon Solution Inc (ISSI); PartNumber: IS61LV12824-10BI-TR; Density: 3M; Packing: Tape & Reel; Speed (ns): 10
footprint ISSI-PBGA-119-14000X22000DE_A (BGA, 119-Balls, Body 22x14mm, Pitch 1.27mm)
part A pins: A2 A11 (in) "Address Inputs", A3 A14 (in) "Address Inputs", A4 A15 (in) "Address Inputs", A5 A16 (in) "Address Inputs", A6 A4 (in) "Address Inputs", B2 A12 (in) "Address Inputs", B3 A13 (in) "Address Inputs", B4 ~{CE1} (in) "Chip Enable Input LOW", B5 A5 (in) "Address Input", B6 A3 (in) "Address Input", C1 I/O16 (io) "Data Inputs/Outputs", C3 CE2 (in) "Chip Enable Input HIGH", C5 ~{CE2} (in) "Chip Enable Input LOW", C7 I/O0 (io) "Data Inputs/Outputs", D1 I/O17 (io) "Data Inputs/Outputs", D7 I/O1 (io) "Data Inputs/Outputs", E1 I/O18 (io) "Data Inputs/Outputs", E7 I/O2 (io) "Data Inputs/Outputs", F1 I/O19 (io) "Data Inputs/Outputs", F7 I/O3 (io) "Data Inputs/Outputs", G1 I/O20 (io) "Data Inputs/Outputs", G7 I/O4 (io) "Data Inputs/Outputs", H1 I/O21 (io) "Data Inputs/Outputs", H7 I/O5 (io) "Data Inputs/Outputs", K1 I/O22 (io) "Data Inputs/Outputs", K7 I/O6 (io) "Data Inputs/Outputs", L1 I/O23 (io) "Data Inputs/Outputs", L7 I/O7 (io) "Data Inputs/Outputs", M1 I/O12 (io) "Data Inputs/Outputs", M7 I/O8 (io) "Data Inputs/Outputs", N1 I/O13 (io) "Data Inputs/Outputs", N7 I/O9 (io) "Data Inputs/Outputs", P1 I/O14 (io) "Data Inputs/Outputs", P7 I/O10 (io) "Data Inputs/Outputs", R1 I/O15 (io) "Data Inputs/Outputs", R7 I/O11 (io) "Data Inputs/Outputs", T2 A10 (in) "Address Inputs", T3 A8 (in) "Address Inputs", T4 ~{WE} (in) "Write Enable Input", T5 A0 (in) "Address Inputs", T6 A1 (in) "Address Inputs", U2 A9 (in) "Address Inputs", U3 A7 (in) "Address Inputs", U4 ~{OE} (in) "Output Enable Input", U5 A6 (in) "Address Inputs", U6 A2 (in) "Address Inputs"
part B pins: D2 VCCQ (power) "I/O Power", D3 GND (power) "Ground", D4 GND (power) "Ground", D5 GND (power) "Ground", D6 VCCQ (power) "I/O Power", E2 GND (power) "Ground", E3 VCC (power) "Power", E4 GND (power) "Ground", E5 VCC (power) "Power", E6 GND (power) "Ground", F2 VCCQ (power) "I/O Power", F3 GND (power) "Ground", F4 GND (power) "Ground", F5 GND (power) "Ground", F6 VCCQ (power) "I/O Power", G2 GND (power) "Ground", G3 VCC (power) "Power", G4 GND (power) "Ground", G5 VCC (power) "Power", G6 GND (power) "Ground", H2 VCCQ (power) "I/O Power", H3 GND (power) "Ground", H4 GND (power) "Ground", H5 GND (power) "Ground", H6 VCCQ (power) "I/O Power", J1 VCCQ (power) "I/O Power", J2 GND (power) "Ground", J3 VCC (power) "Power", J4 GND (power) "Ground", J5 VCC (power) "Power", J6 GND (power) "Ground", J7 VCCQ (power) "I/O Power", K2 VCCQ (power) "I/O Power", K3 GND (power) "Ground", K4 GND (power) "Ground", K5 GND (power) "Ground", K6 VCCQ (power) "I/O Power", L2 GND (power) "Ground", L3 VCC (power) "Power", L4 GND (power) "Ground", L5 VCC (power) "Power", L6 GND (power) "Ground", M2 VCCQ (power) "I/O Power", M3 GND (power) "Ground", M4 GND (power) "Ground", M5 GND (power) "Ground", M6 VCCQ (power) "I/O Power", N2 GND (power) "Ground", N3 VCC (power) "Power", N4 GND (power) "Ground", N5 VCC (power) "Power", N6 GND (power) "Ground", P2 VCCQ (power) "I/O Power", P3 GND (power) "Ground", P4 GND (power) "Ground", P5 GND (power) "Ground", P6 VCCQ (power) "I/O Power"
part C pins: A1 NC "No Connection", A7 NC "No Connection", B1 NC "No Connection", B7 NC "No Connection", C2 NC "No Connection", C4 NC "No Connection", C6 NC "No Connection", R2 NC "No Connection", R3 NC "No Connection", R4 NC "No Connection", R5 NC "No Connection", R6 NC "No Connection", T1 NC "No Connection", T7 NC "No Connection", U1 NC "No Connection", U7 NC "No Connection"

## IS61LV12824-10BL
designator U?
3 M High Speed CMOS SRAM with 3.3 V Supply, 128 K x 24, 0 to 70 degC, 119-Pin BGA (PBGA-119), Pb-Free; Manufacturer: Integrated Silicon Solution Inc (ISSI); PartNumber: IS61LV12824-10BL; Density: 3M; Packing: Tray / Tube; Speed (ns): 10
footprint ISSI-PBGA-119-14000X22000DE_A (BGA, 119-Balls, Body 22x14mm, Pitch 1.27mm)
part A pins: A2 A11 (in) "Address Inputs", A3 A14 (in) "Address Inputs", A4 A15 (in) "Address Inputs", A5 A16 (in) "Address Inputs", A6 A4 (in) "Address Inputs", B2 A12 (in) "Address Inputs", B3 A13 (in) "Address Inputs", B4 ~{CE1} (in) "Chip Enable Input LOW", B5 A5 (in) "Address Input", B6 A3 (in) "Address Input", C1 I/O16 (io) "Data Inputs/Outputs", C3 CE2 (in) "Chip Enable Input HIGH", C5 ~{CE2} (in) "Chip Enable Input LOW", C7 I/O0 (io) "Data Inputs/Outputs", D1 I/O17 (io) "Data Inputs/Outputs", D7 I/O1 (io) "Data Inputs/Outputs", E1 I/O18 (io) "Data Inputs/Outputs", E7 I/O2 (io) "Data Inputs/Outputs", F1 I/O19 (io) "Data Inputs/Outputs", F7 I/O3 (io) "Data Inputs/Outputs", G1 I/O20 (io) "Data Inputs/Outputs", G7 I/O4 (io) "Data Inputs/Outputs", H1 I/O21 (io) "Data Inputs/Outputs", H7 I/O5 (io) "Data Inputs/Outputs", K1 I/O22 (io) "Data Inputs/Outputs", K7 I/O6 (io) "Data Inputs/Outputs", L1 I/O23 (io) "Data Inputs/Outputs", L7 I/O7 (io) "Data Inputs/Outputs", M1 I/O12 (io) "Data Inputs/Outputs", M7 I/O8 (io) "Data Inputs/Outputs", N1 I/O13 (io) "Data Inputs/Outputs", N7 I/O9 (io) "Data Inputs/Outputs", P1 I/O14 (io) "Data Inputs/Outputs", P7 I/O10 (io) "Data Inputs/Outputs", R1 I/O15 (io) "Data Inputs/Outputs", R7 I/O11 (io) "Data Inputs/Outputs", T2 A10 (in) "Address Inputs", T3 A8 (in) "Address Inputs", T4 ~{WE} (in) "Write Enable Input", T5 A0 (in) "Address Inputs", T6 A1 (in) "Address Inputs", U2 A9 (in) "Address Inputs", U3 A7 (in) "Address Inputs", U4 ~{OE} (in) "Output Enable Input", U5 A6 (in) "Address Inputs", U6 A2 (in) "Address Inputs"
part B pins: D2 VCCQ (power) "I/O Power", D3 GND (power) "Ground", D4 GND (power) "Ground", D5 GND (power) "Ground", D6 VCCQ (power) "I/O Power", E2 GND (power) "Ground", E3 VCC (power) "Power", E4 GND (power) "Ground", E5 VCC (power) "Power", E6 GND (power) "Ground", F2 VCCQ (power) "I/O Power", F3 GND (power) "Ground", F4 GND (power) "Ground", F5 GND (power) "Ground", F6 VCCQ (power) "I/O Power", G2 GND (power) "Ground", G3 VCC (power) "Power", G4 GND (power) "Ground", G5 VCC (power) "Power", G6 GND (power) "Ground", H2 VCCQ (power) "I/O Power", H3 GND (power) "Ground", H4 GND (power) "Ground", H5 GND (power) "Ground", H6 VCCQ (power) "I/O Power", J1 VCCQ (power) "I/O Power", J2 GND (power) "Ground", J3 VCC (power) "Power", J4 GND (power) "Ground", J5 VCC (power) "Power", J6 GND (power) "Ground", J7 VCCQ (power) "I/O Power", K2 VCCQ (power) "I/O Power", K3 GND (power) "Ground", K4 GND (power) "Ground", K5 GND (power) "Ground", K6 VCCQ (power) "I/O Power", L2 GND (power) "Ground", L3 VCC (power) "Power", L4 GND (power) "Ground", L5 VCC (power) "Power", L6 GND (power) "Ground", M2 VCCQ (power) "I/O Power", M3 GND (power) "Ground", M4 GND (power) "Ground", M5 GND (power) "Ground", M6 VCCQ (power) "I/O Power", N2 GND (power) "Ground", N3 VCC (power) "Power", N4 GND (power) "Ground", N5 VCC (power) "Power", N6 GND (power) "Ground", P2 VCCQ (power) "I/O Power", P3 GND (power) "Ground", P4 GND (power) "Ground", P5 GND (power) "Ground", P6 VCCQ (power) "I/O Power"
part C pins: A1 NC "No Connection", A7 NC "No Connection", B1 NC "No Connection", B7 NC "No Connection", C2 NC "No Connection", C4 NC "No Connection", C6 NC "No Connection", R2 NC "No Connection", R3 NC "No Connection", R4 NC "No Connection", R5 NC "No Connection", R6 NC "No Connection", T1 NC "No Connection", T7 NC "No Connection", U1 NC "No Connection", U7 NC "No Connection"

## IS61LV12824-10BL-TR
designator U?
3 M High Speed CMOS SRAM with 3.3 V Supply, 128 K x 24, 0 to 70 degC, 119-Pin BGA (PBGA-119), Pb-Free; Manufacturer: Integrated Silicon Solution Inc (ISSI); PartNumber: IS61LV12824-10BL-TR; Density: 3M; Packing: Tape & Reel; Speed (ns): 10
footprint ISSI-PBGA-119-14000X22000DE_A (BGA, 119-Balls, Body 22x14mm, Pitch 1.27mm)
part A pins: A2 A11 (in) "Address Inputs", A3 A14 (in) "Address Inputs", A4 A15 (in) "Address Inputs", A5 A16 (in) "Address Inputs", A6 A4 (in) "Address Inputs", B2 A12 (in) "Address Inputs", B3 A13 (in) "Address Inputs", B4 ~{CE1} (in) "Chip Enable Input LOW", B5 A5 (in) "Address Input", B6 A3 (in) "Address Input", C1 I/O16 (io) "Data Inputs/Outputs", C3 CE2 (in) "Chip Enable Input HIGH", C5 ~{CE2} (in) "Chip Enable Input LOW", C7 I/O0 (io) "Data Inputs/Outputs", D1 I/O17 (io) "Data Inputs/Outputs", D7 I/O1 (io) "Data Inputs/Outputs", E1 I/O18 (io) "Data Inputs/Outputs", E7 I/O2 (io) "Data Inputs/Outputs", F1 I/O19 (io) "Data Inputs/Outputs", F7 I/O3 (io) "Data Inputs/Outputs", G1 I/O20 (io) "Data Inputs/Outputs", G7 I/O4 (io) "Data Inputs/Outputs", H1 I/O21 (io) "Data Inputs/Outputs", H7 I/O5 (io) "Data Inputs/Outputs", K1 I/O22 (io) "Data Inputs/Outputs", K7 I/O6 (io) "Data Inputs/Outputs", L1 I/O23 (io) "Data Inputs/Outputs", L7 I/O7 (io) "Data Inputs/Outputs", M1 I/O12 (io) "Data Inputs/Outputs", M7 I/O8 (io) "Data Inputs/Outputs", N1 I/O13 (io) "Data Inputs/Outputs", N7 I/O9 (io) "Data Inputs/Outputs", P1 I/O14 (io) "Data Inputs/Outputs", P7 I/O10 (io) "Data Inputs/Outputs", R1 I/O15 (io) "Data Inputs/Outputs", R7 I/O11 (io) "Data Inputs/Outputs", T2 A10 (in) "Address Inputs", T3 A8 (in) "Address Inputs", T4 ~{WE} (in) "Write Enable Input", T5 A0 (in) "Address Inputs", T6 A1 (in) "Address Inputs", U2 A9 (in) "Address Inputs", U3 A7 (in) "Address Inputs", U4 ~{OE} (in) "Output Enable Input", U5 A6 (in) "Address Inputs", U6 A2 (in) "Address Inputs"
part B pins: D2 VCCQ (power) "I/O Power", D3 GND (power) "Ground", D4 GND (power) "Ground", D5 GND (power) "Ground", D6 VCCQ (power) "I/O Power", E2 GND (power) "Ground", E3 VCC (power) "Power", E4 GND (power) "Ground", E5 VCC (power) "Power", E6 GND (power) "Ground", F2 VCCQ (power) "I/O Power", F3 GND (power) "Ground", F4 GND (power) "Ground", F5 GND (power) "Ground", F6 VCCQ (power) "I/O Power", G2 GND (power) "Ground", G3 VCC (power) "Power", G4 GND (power) "Ground", G5 VCC (power) "Power", G6 GND (power) "Ground", H2 VCCQ (power) "I/O Power", H3 GND (power) "Ground", H4 GND (power) "Ground", H5 GND (power) "Ground", H6 VCCQ (power) "I/O Power", J1 VCCQ (power) "I/O Power", J2 GND (power) "Ground", J3 VCC (power) "Power", J4 GND (power) "Ground", J5 VCC (power) "Power", J6 GND (power) "Ground", J7 VCCQ (power) "I/O Power", K2 VCCQ (power) "I/O Power", K3 GND (power) "Ground", K4 GND (power) "Ground", K5 GND (power) "Ground", K6 VCCQ (power) "I/O Power", L2 GND (power) "Ground", L3 VCC (power) "Power", L4 GND (power) "Ground", L5 VCC (power) "Power", L6 GND (power) "Ground", M2 VCCQ (power) "I/O Power", M3 GND (power) "Ground", M4 GND (power) "Ground", M5 GND (power) "Ground", M6 VCCQ (power) "I/O Power", N2 GND (power) "Ground", N3 VCC (power) "Power", N4 GND (power) "Ground", N5 VCC (power) "Power", N6 GND (power) "Ground", P2 VCCQ (power) "I/O Power", P3 GND (power) "Ground", P4 GND (power) "Ground", P5 GND (power) "Ground", P6 VCCQ (power) "I/O Power"
part C pins: A1 NC "No Connection", A7 NC "No Connection", B1 NC "No Connection", B7 NC "No Connection", C2 NC "No Connection", C4 NC "No Connection", C6 NC "No Connection", R2 NC "No Connection", R3 NC "No Connection", R4 NC "No Connection", R5 NC "No Connection", R6 NC "No Connection", T1 NC "No Connection", T7 NC "No Connection", U1 NC "No Connection", U7 NC "No Connection"

## IS61LV12824-10TQ
designator U?
3 M High Speed CMOS SRAM with 3.3 V Supply, 128 K x 24, 0 to 70 degC, 100-Pin QFP (TQFP-100); Manufacturer: Integrated Silicon Solution Inc (ISSI); PartNumber: IS61LV12824-10TQ; Density: 3M; Packing: Tray / Tube; Speed (ns): 10
footprint ISSI-TQFP-100-20000X14000DE_N (QFP, 100-Leads, Body 20x14mm, Pitch 0.65mm, IPC Medium Density)
part A pins: 4 I/O16 (io) "Data Input/Output", 5 I/O17 (io) "Data Input/Output", 8 I/O18 (io) "Data Input/Output", 9 I/O19 (io) "Data Input/Output", 12 I/O20 (io) "Data Input/Output", 13 I/O21 (io) "Data Input/Output", 18 I/O22 (io) "Data Input/Output", 19 I/O23 (io) "Data Input/Output", 22 I/O12 (io) "Data Input/Output", 23 I/O13 (io) "Data Input/Output", 26 I/O14 (io) "Data Input/Output", 27 I/O15 (io) "Data Input/Output", 35 A10 (in) "Address Input", 36 A9 (in) "Address Input", 37 A8 (in) "Address Input", 38 A7 (in) "Address Input", 39 ~{OE} (in) "Output Enable Input", 42 ~{WE} (in) "Write Enable Input", 43 A6 (in) "Address Input", 44 A0 (in) "Address Input", 45 A1 (in) "Address Input", 46 A2 (in) "Address Input", 54 I/O11 (io) "Data Input/Output", 55 I/O10 (io) "Data Input/Output", 58 I/O9 (io) "Data Input/Output", 59 I/O8 (io) "Data Input/Output", 62 I/O7 (io) "Data Input/Output", 63 I/O6 (io) "Data Input/Output", 68 I/O5 (io) "Data Input/Output", 69 I/O4 (io) "Data Input/Output", 72 I/O3 (io) "Data Input/Output", 73 I/O2 (io) "Data Input/Output", 76 I/O1 (io) "Data Input/Output", 77 I/O0 (io) "Data Input/Output", 85 A3 (in) "Address Input", 86 A4 (in) "Address Input", 87 A5 (in) "Address Input", 88 A16 (in) "Address Input", 89 ~{CE1} (in) "Chip Enable Input LOW", 90 ~{CE2} (in) "Chip Enable Input LOW", 93 CE2 (in) "Chip Enable Input HIGH", 94 A15 (in) "Address Input", 95 A14 (in) "Address Input", 96 A13 (in) "Address Input", 97 A12 (in) "Address Input", 98 A11 (in) "Address Input"
part B pins: 2 VCC (power) "Power", 3 GND (power) "Ground", 6 GND (power) "Ground", 7 VCCQ (power) "I/O Power", 10 GND (power) "Ground", 11 VCCQ (power) "I/O Power", 14 VCC (power) "Power", 17 GND (power) "Ground", 20 VCCQ (power) "I/O Power", 21 GND (power) "Ground", 24 VCCQ (power) "I/O Power", 25 GND (power) "Ground", 28 VCC (power) "Power", 29 GND (power) "Ground", 40 GND (power) "Ground", 41 VCC (power) "Power", 52 GND (power) "Ground", 53 VCC (power) "Power", 56 GND (power) "Ground", 57 VCCQ (power) "I/O Power", 60 GND (power) "Ground", 61 VCCQ (power) "I/O Power", 64 GND (power) "Ground", 67 VCC (power) "Power", 70 VCCQ (power) "I/O Power", 71 GND (power) "Ground", 74 VCCQ (power) "I/O Power", 75 GND (power) "Ground", 78 GND (power) "Ground", 79 VCC (power) "Power", 91 GND (power) "Ground", 92 VCC (power) "Power"
part C pins: 1 NC "No Connection", 15 NC "No Connection", 16 NC "No Connection", 30 NC "No Connection", 31 NC "No Connection", 32 NC "No Connection", 33 NC "No Connection", 34 NC "No Connection", 47 NC "No Connection", 48 NC "No Connection", 49 NC "No Connection", 50 NC "No Connection", 51 NC "No Connection", 65 NC "No Connection", 66 NC "No Connection", 80 NC "No Connection", 81 NC "No Connection", 82 NC "No Connection", 83 NC "No Connection", 84 NC "No Connection", 99 NC "No Connection", 100 NC "No Connection"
